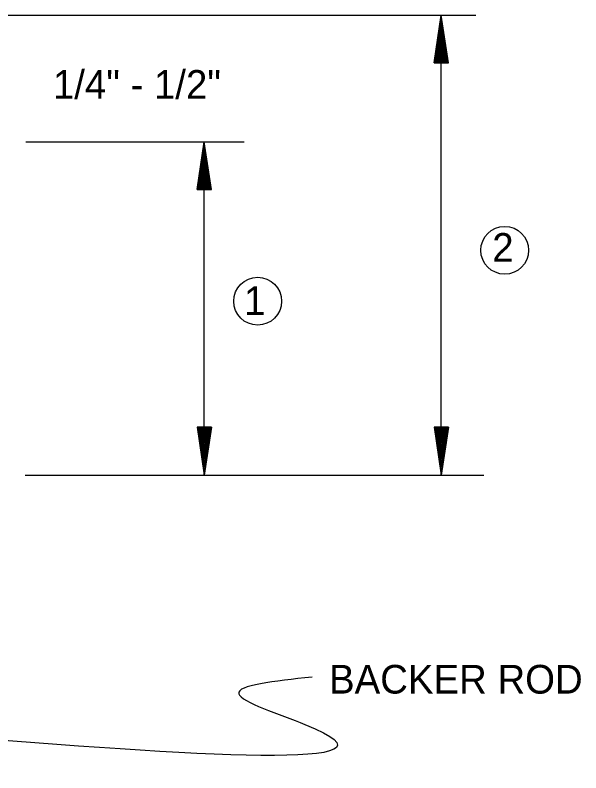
# Model space of a CAD drawing. Extents: x 1929624 to 1935547, y 596315 to 605721.
# Drawn here: x 1933966.5 to 1934084.8, y 602559.6 to 602718.1 of the extents above; entities that cross this region are included whole.
import ezdxf

# ---------------------------------------------------------------- set-up
doc = ezdxf.new("R2010")
doc.units = 0
doc.layers.add('R_Draft', color=7, linetype='Continuous')

msp = doc.modelspace()

# ---------------------------------------------------------------- linework, layer by layer
at = {"layer": 'R_Draft'}
for p, q in [((1933963.97, 602718.06), (1934062.8, 602718.06)), ((1934054.06, 602708.06), (1934055.56, 602718.06)), ((1934055.56, 602621.84), (1934055.56, 602718.06)), ((1934057.06, 602708.06), (1934055.56, 602718.06)), ((1934054.31, 602708.06), (1934055.56, 602716.39)), ((1934056.81, 602708.06), (1934055.56, 602716.39)), ((1934054.56, 602708.06), (1934055.56, 602714.67)), ((1934056.55, 602708.06), (1934055.56, 602714.67)), ((1934054.81, 602708.06), (1934055.56, 602713.01)), ((1934056.3, 602708.06), (1934055.56, 602713.01)), ((1934055.07, 602708.06), (1934055.56, 602711.31)), ((1934056.05, 602708.06), (1934055.56, 602711.31)), ((1934055.32, 602708.06), (1934055.56, 602709.64)), ((1934055.79, 602708.06), (1934055.56, 602709.64)), ((1934054.06, 602708.06), (1934057.06, 602708.06)), ((1933968.69, 602691.59), (1934014.35, 602691.59)), ((1934004.5, 602681.59), (1934006, 602691.59)), ((1934006, 602621.84), (1934006, 602691.59)), ((1934007.5, 602681.59), (1934006, 602691.59)), ((1934004.75, 602681.59), (1934006, 602689.92)), ((1934007.25, 602681.59), (1934006, 602689.92)), ((1934005, 602681.59), (1934006, 602688.2)), ((1934006.99, 602681.59), (1934006, 602688.2)), ((1934005.25, 602681.59), (1934006, 602686.53)), ((1934006.74, 602681.59), (1934006, 602686.53)), ((1934005.51, 602681.59), (1934006, 602684.84)), ((1934006.49, 602681.59), (1934006, 602684.84)), ((1934005.76, 602681.59), (1934006, 602683.17)), ((1934006.23, 602681.59), (1934006, 602683.17)), ((1934004.5, 602681.59), (1934007.5, 602681.59)), ((1934004.5, 602631.84), (1934006, 602621.84)), ((1934007.5, 602631.84), (1934004.5, 602631.84)), ((1934004.75, 602631.84), (1934006, 602623.51)), ((1934005, 602631.84), (1934006, 602625.23)), ((1934005.25, 602631.84), (1934006, 602626.9)), ((1934005.51, 602631.84), (1934006, 602628.59)), ((1934005.76, 602631.84), (1934006, 602630.26)), ((1934007.5, 602631.84), (1934006, 602621.84)), ((1934006.48, 602631.84), (1934006, 602628.59)), ((1934006.99, 602631.84), (1934006, 602625.23)), ((1934007.25, 602631.84), (1934006, 602623.51)), ((1934006.74, 602631.84), (1934006, 602626.9)), ((1934006.23, 602631.84), (1934006, 602630.26)), ((1934054.06, 602631.84), (1934055.56, 602621.84)), ((1934057.06, 602631.84), (1934054.06, 602631.84)), ((1934054.31, 602631.84), (1934055.56, 602623.51)), ((1934054.56, 602631.84), (1934055.56, 602625.23)), ((1934054.81, 602631.84), (1934055.56, 602626.9)), ((1934055.07, 602631.84), (1934055.56, 602628.59)), ((1934055.32, 602631.84), (1934055.56, 602630.26)), ((1934057.06, 602631.84), (1934055.56, 602621.84)), ((1934056.04, 602631.84), (1934055.56, 602628.59)), ((1934056.55, 602631.84), (1934055.56, 602625.23)), ((1934056.81, 602631.84), (1934055.56, 602623.51)), ((1934056.3, 602631.84), (1934055.56, 602626.9)), ((1934055.79, 602631.84), (1934055.56, 602630.26)), ((1933968.55, 602621.84), (1934064.47, 602621.84))]:
    msp.add_line(p, q, dxfattribs=at)
for centre in [(1934068.84, 602668.87), (1934017.18, 602658.22)]:
    msp.add_circle(centre, 5, dxfattribs=at)
msp.add_spline([(1934028.54, 602579.58), (1934013.22, 602576.12), (1934027.06, 602569.69), (1933951.9, 602567.22)], degree=3, dxfattribs=at)

# ---------------------------------------------------------------- texts
for s, p in [('1/4" - 1/2"', (1933974.36, 602700.57)), ('2', (1934066.24, 602666.47)), ('1', (1934014.33, 602655.33)), ('BACKER ROD', (1934032.1, 602576.14))]:
    msp.add_text(s, height=6, dxfattribs=at).set_placement(p)

doc.saveas('drawing.dxf')
